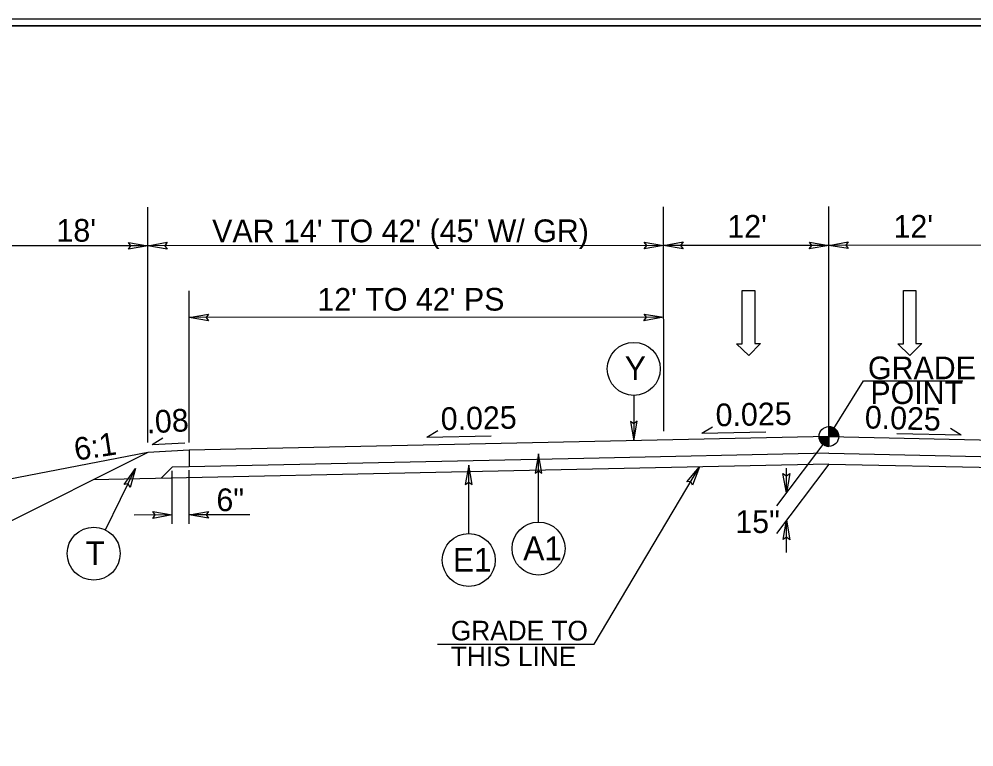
# Model space of a CAD drawing. Extents: x 2241081 to 2251104, y 658534 to 663427.
# Drawn here: x 2248103.9 to 2248450.9, y 661534.7 to 661799.3 of the extents above; entities that cross this region are included whole.
import ezdxf

# ---------------------------------------------------------------- set-up
doc = ezdxf.new("R2010")
doc.units = 0
for name, color, linetype in [('Old_Level_1', 7, 'Continuous'), ('Old_Level_11', 7, 'Continuous'), ('Old_Level_2', 7, 'Continuous'), ('Old_Level_3', 7, 'Continuous'), ('Prop Dimension Text', 7, 'Continuous'), ('Prop Lane Arrow CELL', 7, 'Continuous'), ('Sheet Plan CELL', 7, 'Continuous'), ('Sheet Plot Border Inside CELL', 7, 'Continuous'), ('Typical Arrow Superelevation CELL', 7, 'Continuous'), ('Typical Berm Information CELL', 7, 'Continuous'), ('Typical Grade Point Symbol CELL', 7, 'Continuous'), ('Typical Hinge Slope Interstate CELL', 7, 'Continuous'), ('Typical ID Circle CELL', 7, 'Continuous'), ('Typical Terminator CELL', 7, 'Continuous'), ('Typical Text Grade Point CELL', 7, 'Continuous'), ('Typical Text ID Circle CELL', 7, 'Continuous')]:
    doc.layers.add(name, color=color, linetype=linetype)

msp = doc.modelspace()

# ---------------------------------------------------------------- linework, layer by layer
at = {"layer": 'Old_Level_1'}
msp.add_line((2248150.7, 661641.73), (2248041.87, 661620.78), dxfattribs=at)
at = {"layer": 'Old_Level_11'}
msp.add_line((2248312.94, 661571.98), (2248351.16, 661636.52), dxfattribs=at)
at = {"layer": 'Old_Level_2'}
for p, q in [((2248398.2, 661647.53), (2248165.7, 661642.55)), ((2248398.2, 661647.53), (2248458.42, 661646.24)), ((2248165.7, 661642.55), (2248150.7, 661641.73)), ((2248165.7, 661642.55), (2248165.7, 661636.5)), ((2248309.11, 661639.57), (2248165.7, 661636.5)), ((2248398.2, 661641.48), (2248309.11, 661639.57)), ((2248398.2, 661641.48), (2248512.51, 661639.03)), ((2248159.52, 661636.37), (2248155.48, 661632.33)), ((2248165.7, 661636.5), (2248159.52, 661636.37)), ((2248398.2, 661637.53), (2248277.97, 661634.95)), ((2248398.2, 661637.53), (2248543.15, 661634.42)), ((2248277.97, 661634.95), (2248130.85, 661631.8))]:
    msp.add_line(p, q, dxfattribs=at)
at = {"layer": 'Prop Dimension Text'}
for p, q in [((2248150.7, 661645.35), (2248150.65, 661730.94)), ((2248338.2, 661649.44), (2248338.15, 661731.06)), ((2248338.2, 661649.44), (2248338.15, 661731.06)), ((2248398.15, 661724.32), (2248398.15, 661731.09)), ((2248398.2, 661645.5), (2248398.15, 661730.41)), ((2248150.7, 661716.87), (2248092.69, 661716.87)), ((2248338.15, 661716.99), (2248150.65, 661716.87)), ((2248398.15, 661717.02), (2248338.15, 661716.99)), ((2248458.15, 661717.06), (2248398.15, 661717.02)), ((2248165.7, 661645.36), (2248165.66, 661700.44)), ((2248338.05, 661690.86), (2248165.67, 661690.75)), ((2248398.2, 661647.53), (2248379.19, 661622.32)), ((2248165.71, 661615.84), (2248165.7, 661635.28)), ((2248398.2, 661637.53), (2248379.19, 661612.32)), ((2248382.76, 661627.06), (2248382.76, 661636.05)), ((2248159.53, 661615.84), (2248159.53, 661635.07)), ((2248159.53, 661619), (2248145.66, 661618.99)), ((2248187.71, 661619.02), (2248165.7, 661619.01)), ((2248382.76, 661605.36), (2248382.76, 661617.06)), ((2248255.98, 661572.02), (2248312.94, 661571.98))]:
    msp.add_line(p, q, dxfattribs=at)
at = {"layer": 'Prop Lane Arrow CELL'}
for p, q in [((2248366.7, 661681.27), (2248366.69, 661700.57)), ((2248366.69, 661700.57), (2248371.24, 661700.57)), ((2248371.24, 661700.57), (2248371.25, 661681.28)), ((2248425.3, 661681.27), (2248425.29, 661700.57)), ((2248425.29, 661700.57), (2248429.84, 661700.57)), ((2248429.84, 661700.57), (2248429.85, 661681.28)), ((2248369.05, 661676.93), (2248364.63, 661681.27)), ((2248364.63, 661681.27), (2248366.7, 661681.27)), ((2248373.32, 661681.28), (2248369.05, 661676.93)), ((2248371.25, 661681.28), (2248373.32, 661681.28)), ((2248427.65, 661676.93), (2248423.24, 661681.27)), ((2248423.24, 661681.27), (2248425.3, 661681.27)), ((2248431.92, 661681.28), (2248427.65, 661676.93)), ((2248429.85, 661681.28), (2248431.92, 661681.28))]:
    msp.add_line(p, q, dxfattribs=at)
at = {"layer": 'Sheet Plan CELL'}
for points in [[(2247801.99, 660746.78), (2247801.97, 661796.75), (2249101.96, 661796.79), (2249101.97, 661646.73), (2249302.01, 661646.71), (2249302.01, 660746.78)], [(2249302.03, 661796.78), (2247802, 661796.78), (2247801.99, 660746.78), (2249302.01, 660746.78)]]:
    msp.add_lwpolyline(points, close=True, dxfattribs=at)
at = {"layer": 'Sheet Plot Border Inside CELL'}
msp.add_lwpolyline([(2247648.51, 660744.27), (2249314.49, 660744.28), (2249314.51, 661799.26), (2247648.51, 661799.27)], close=True, dxfattribs=at)
at = {"layer": 'Typical Arrow Superelevation CELL'}
for p, q in [((2248252.14, 661647.33), (2248256.06, 661649.7)), ((2248352.03, 661648.71), (2248355.94, 661651.08)), ((2248352.03, 661648.71), (2248375.33, 661649.18)), ((2248446.25, 661648.04), (2248442.34, 661650.41)), ((2248152.28, 661644.59), (2248156.11, 661647.09)), ((2248252.14, 661647.33), (2248275.45, 661647.8)), ((2248446.25, 661648.04), (2248422.95, 661648.51)), ((2248152.28, 661644.59), (2248164.19, 661645.24))]:
    msp.add_line(p, q, dxfattribs=at)
at = {"layer": 'Typical Grade Point Symbol CELL'}
for p, q in [((2248398.2, 661647.53), (2248410.78, 661667.71)), ((2248398.2, 661651.11), (2248398.2, 661647.53)), ((2248398.2, 661647.53), (2248398.2, 661651.11)), ((2248394.62, 661647.53), (2248398.2, 661647.53)), ((2248398.2, 661647.53), (2248398.2, 661643.95)), ((2248401.78, 661647.53), (2248398.2, 661647.53))]:
    msp.add_line(p, q, dxfattribs=at)
for points in [[(2248398.25, 661647.53), (2248398.25, 661651.11), (2248398.25, 661651.11)], [(2248398.32, 661647.53), (2248398.32, 661651.11)], [(2248398.4, 661647.53), (2248398.4, 661651.1)], [(2248398.47, 661647.53), (2248398.47, 661651.1)], [(2248398.54, 661647.53), (2248398.54, 661651.09)], [(2248398.61, 661647.53), (2248398.61, 661651.09)], [(2248398.68, 661647.53), (2248398.68, 661651.08)], [(2248398.75, 661647.53), (2248398.75, 661651.06)], [(2248398.83, 661647.53), (2248398.83, 661651.06)], [(2248398.9, 661647.53), (2248398.9, 661651.04)], [(2248398.97, 661647.53), (2248398.97, 661651.02)], [(2248399.04, 661647.53), (2248399.04, 661651.01)], [(2248399.11, 661647.53), (2248399.11, 661650.99)], [(2248399.18, 661647.53), (2248399.18, 661650.97)], [(2248399.26, 661647.53), (2248399.26, 661650.95)], [(2248399.33, 661647.53), (2248399.33, 661650.93)], [(2248399.4, 661647.53), (2248399.4, 661650.9)], [(2248399.47, 661647.53), (2248399.47, 661650.88)], [(2248399.54, 661647.53), (2248399.54, 661650.85)], [(2248399.61, 661647.53), (2248399.61, 661650.82)], [(2248399.68, 661647.53), (2248399.68, 661650.79)], [(2248399.76, 661647.53), (2248399.76, 661650.75)], [(2248399.83, 661647.53), (2248399.83, 661650.72)], [(2248399.9, 661647.53), (2248399.9, 661650.68)], [(2248399.97, 661647.53), (2248399.97, 661650.64)], [(2248400.04, 661647.53), (2248400.04, 661650.6)], [(2248400.11, 661647.53), (2248400.11, 661650.55)], [(2248400.19, 661647.53), (2248400.19, 661650.51)], [(2248400.26, 661647.53), (2248400.26, 661650.46)], [(2248400.33, 661647.53), (2248400.33, 661650.41)], [(2248400.4, 661647.53), (2248400.4, 661650.36)], [(2248400.47, 661647.53), (2248400.47, 661650.3)], [(2248400.54, 661647.53), (2248400.54, 661650.24)], [(2248400.62, 661647.53), (2248400.62, 661650.17)], [(2248400.69, 661647.53), (2248400.69, 661650.11)], [(2248400.76, 661647.53), (2248400.76, 661650.04)], [(2248400.83, 661647.53), (2248400.83, 661649.96)], [(2248400.9, 661647.53), (2248400.9, 661649.88)], [(2248400.97, 661647.53), (2248400.97, 661649.79)], [(2248401.05, 661647.53), (2248401.05, 661649.7)], [(2248401.12, 661647.53), (2248401.12, 661649.61)], [(2248401.19, 661647.53), (2248401.19, 661649.5)], [(2248401.26, 661647.53), (2248401.26, 661649.39)], [(2248401.33, 661647.53), (2248401.33, 661649.26)], [(2248401.4, 661647.53), (2248401.4, 661649.13)], [(2248394.66, 661647.02), (2248394.66, 661647.53)], [(2248394.73, 661646.66), (2248394.73, 661647.53)], [(2248394.8, 661646.41), (2248394.8, 661647.53)], [(2248394.87, 661646.21), (2248394.87, 661647.53)], [(2248394.94, 661646.04), (2248394.94, 661647.53)], [(2248395.01, 661645.89), (2248395.01, 661647.53)], [(2248395.09, 661645.76), (2248395.09, 661647.53)], [(2248395.16, 661645.64), (2248395.16, 661647.53)], [(2248395.23, 661645.53), (2248395.23, 661647.53)], [(2248395.3, 661645.43), (2248395.3, 661647.53)], [(2248395.37, 661645.33), (2248395.37, 661647.53)], [(2248395.44, 661645.25), (2248395.44, 661647.53)], [(2248395.52, 661645.16), (2248395.52, 661647.53)], [(2248395.59, 661645.08), (2248395.59, 661647.53)], [(2248395.66, 661645.01), (2248395.66, 661647.53)], [(2248395.73, 661644.94), (2248395.73, 661647.53)], [(2248395.8, 661644.87), (2248395.8, 661647.53)], [(2248395.87, 661644.81), (2248395.87, 661647.53)], [(2248395.94, 661644.75), (2248395.94, 661647.53)], [(2248396.02, 661644.69), (2248396.02, 661647.53)], [(2248396.09, 661644.64), (2248396.09, 661647.53)], [(2248396.16, 661644.59), (2248396.16, 661647.53)], [(2248396.23, 661644.54), (2248396.23, 661647.53)], [(2248396.3, 661644.49), (2248396.3, 661647.53)], [(2248396.37, 661644.45), (2248396.37, 661647.53)], [(2248396.45, 661644.41), (2248396.45, 661647.53)], [(2248396.52, 661644.37), (2248396.52, 661647.53)], [(2248396.59, 661644.33), (2248396.59, 661647.53)], [(2248396.66, 661644.3), (2248396.66, 661647.53)], [(2248396.73, 661644.27), (2248396.73, 661647.53)], [(2248396.8, 661644.24), (2248396.8, 661647.53)], [(2248396.88, 661644.2), (2248396.88, 661647.53)], [(2248396.95, 661644.17), (2248396.95, 661647.53)], [(2248397.02, 661644.15), (2248397.02, 661647.53)], [(2248397.09, 661644.12), (2248397.09, 661647.53)], [(2248397.16, 661644.1), (2248397.16, 661647.53)], [(2248397.23, 661644.08), (2248397.23, 661647.53)], [(2248397.31, 661644.06), (2248397.31, 661647.53)], [(2248397.38, 661644.05), (2248397.38, 661647.53)], [(2248397.45, 661644.03), (2248397.45, 661647.53)], [(2248397.52, 661644.01), (2248397.52, 661647.53)], [(2248397.59, 661644), (2248397.59, 661647.53)], [(2248397.66, 661643.99), (2248397.66, 661647.53)], [(2248397.74, 661643.98), (2248397.74, 661647.53)], [(2248397.81, 661643.97), (2248397.81, 661647.53)], [(2248397.88, 661643.97), (2248397.88, 661647.53)], [(2248397.95, 661643.96), (2248397.95, 661647.53)], [(2248398.02, 661643.96), (2248398.02, 661647.53)], [(2248398.09, 661643.95), (2248398.09, 661647.53)], [(2248398.16, 661643.95), (2248398.16, 661643.95), (2248398.16, 661647.53)], [(2248401.48, 661647.53), (2248401.48, 661648.98)], [(2248401.55, 661647.53), (2248401.55, 661648.81)], [(2248401.62, 661647.53), (2248401.62, 661648.6)], [(2248401.69, 661647.53), (2248401.69, 661648.34)], [(2248401.76, 661647.53), (2248401.76, 661647.92)]]:
    msp.add_lwpolyline(points, dxfattribs=at)
msp.add_circle((2248398.2, 661647.53), 3.58, dxfattribs=at)
for start, end in [(359.9905, 89.9905), (179.9905, 269.9905)]:
    msp.add_arc((2248398.2, 661647.53), 3.58, start, end, dxfattribs=at)
at = {"layer": 'Typical Hinge Slope Interstate CELL'}
msp.add_line((2248150.7, 661641.73), (2248038.2, 661585.48), dxfattribs=at)
at = {"layer": 'Typical ID Circle CELL'}
for p, q in [((2248327.28, 661662.49), (2248327.28, 661646.01)), ((2248292.68, 661616.42), (2248292.68, 661641.27)), ((2248135.25, 661613.58), (2248146.24, 661635.87)), ((2248267.32, 661612.25), (2248267.32, 661637.1))]:
    msp.add_line(p, q, dxfattribs=at)
for centre in [(2248327.28, 661672.1), (2248131, 661604.95), (2248292.68, 661606.8), (2248267.32, 661602.63)]:
    msp.add_circle(centre, 9.62, dxfattribs=at)
at = {"layer": 'Typical Terminator CELL'}
for points in [[(2248143.67, 661718.08), (2248150.7, 661716.87), (2248143.63, 661715.62), (2248144.53, 661716.87)], [(2248157.69, 661715.67), (2248150.65, 661716.87), (2248157.72, 661718.13), (2248156.83, 661716.88)], [(2248331.12, 661718.19), (2248338.15, 661716.99), (2248331.09, 661715.73), (2248331.98, 661716.98)], [(2248345.19, 661715.78), (2248338.15, 661716.99), (2248345.22, 661718.24), (2248344.33, 661716.99)], [(2248391.12, 661718.23), (2248398.15, 661717.02), (2248391.09, 661715.77), (2248391.98, 661717.02)], [(2248405.19, 661715.82), (2248398.15, 661717.02), (2248405.22, 661718.28), (2248404.33, 661717.03)], [(2248172.7, 661689.55), (2248165.67, 661690.75), (2248172.74, 661692.01), (2248171.84, 661690.76)], [(2248331.02, 661692.06), (2248338.05, 661690.86), (2248330.98, 661689.6), (2248331.88, 661690.85)], [(2248326.07, 661653.04), (2248327.28, 661646.01), (2248328.53, 661653.08), (2248327.28, 661652.18)], [(2248293.89, 661634.24), (2248292.68, 661641.27), (2248291.43, 661634.2), (2248292.68, 661635.1)], [(2248142.05, 661630.1), (2248146.24, 661635.87), (2248144.24, 661628.97), (2248143.51, 661630.33)], [(2248268.53, 661630.07), (2248267.32, 661637.1), (2248266.07, 661630.03), (2248267.32, 661630.93)], [(2248346.54, 661631.09), (2248351.16, 661636.52), (2248348.63, 661629.8), (2248348.02, 661631.21)], [(2248383.97, 661634.09), (2248382.76, 661627.06), (2248381.51, 661634.13), (2248382.76, 661633.23)], [(2248152.5, 661620.21), (2248159.53, 661619), (2248152.46, 661617.75), (2248153.36, 661619)], [(2248172.73, 661617.8), (2248165.7, 661619.01), (2248172.77, 661620.26), (2248171.87, 661619.01)], [(2248381.55, 661610.03), (2248382.76, 661617.06), (2248384.01, 661609.99), (2248382.76, 661610.88)]]:
    msp.add_lwpolyline(points, close=True, dxfattribs=at)
at = {"layer": 'Typical Text Grade Point CELL'}
msp.add_line((2248410.78, 661667.71), (2248446.91, 661667.73), dxfattribs=at)

# ---------------------------------------------------------------- texts
at = {"layer": 'Old_Level_3'}
for s, p in [('GRADE TO', (2248260.81, 661573.4)), ('THIS LINE', (2248260.81, 661564.05))]:
    msp.add_text(s, height=7.131, rotation=359.9999, dxfattribs=at).set_placement(p)
at = {"layer": 'Prop Dimension Text'}
for s, rotation, p in [("18'", 359.9999, (2248117.49, 661718.34)), ("VAR 14' TO 42' (45' W/ GR)", 0.0349, (2248174.07, 661718.11)), ("12'", 0.0349, (2248361.3, 661719.8)), ("12'", 0.0349, (2248421.69, 661719.8)), ("12' TO 42' PS", 0.0349, (2248212.3, 661693.25)), ('6:1', 8.8656, (2248124.55, 661638.69)), ('6"', 0.0349, (2248175.61, 661620.4)), ('15"', 359.9999, (2248364.2, 661612.46))]:
    msp.add_text(s, height=8.25, rotation=rotation, dxfattribs=at).set_placement(p)
at = {"layer": 'Typical Berm Information CELL'}
for s, rotation, p in [('0.025', 1.1459, (2248357.11, 661651.22)), ('.08', 3.1445, (2248150.41, 661648.62)), ('0.025', 1.1459, (2248257.22, 661649.84)), ('0.025', 358.1916, (2248411.15, 661650.5))]:
    msp.add_text(s, height=8.25, rotation=rotation, dxfattribs=at).set_placement(p)
at = {"layer": 'Typical Text Grade Point CELL'}
for s, p in [('GRADE', (2248412.4, 661668.33)), ('POINT', (2248413.28, 661659.33))]:
    msp.add_text(s, height=8.25, rotation=0.0349, dxfattribs=at).set_placement(p)
at = {"layer": 'Typical Text ID Circle CELL'}
for s, height, p in [('Y', 8.61, (2248324.02, 661668.03)), ('A1', 8.608, (2248287.12, 661602.57)), ('T', 8.61, (2248128.04, 661600.79)), ('E1', 8.608, (2248261.57, 661598.4))]:
    msp.add_text(s, height=height, rotation=359.9999, dxfattribs=at).set_placement(p)

doc.saveas('drawing.dxf')
